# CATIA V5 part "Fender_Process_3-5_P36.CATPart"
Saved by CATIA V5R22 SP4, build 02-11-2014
Part number: Fender
Bounding box of the stored display mesh (mm): x -800 to 0, y -40 to 122.298, z 0 to 580
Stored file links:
  C:\DATA\Car_ASSY\教育モデル\3_SOL\Fender_Process_3-5_P36.CATPart
  C:\DATA\Car_ASSY\教育モデル\3_SOL\Car_Fender.CATPart
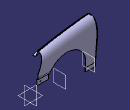
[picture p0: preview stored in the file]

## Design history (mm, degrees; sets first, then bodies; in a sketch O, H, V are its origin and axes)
Set1
  Plane1: type Offset, RefPlane yz-plane, Offset 400, reversed
  Plane2: type Offset, RefPlane Plane1, Offset 400, reversed
Body1 (main body)
Body2
  Sketch1 on yz-plane, origin (0, 0, 0), H (0, 1, 0), V (0, 0, 1)
    point P4 (100, 50)
    point P5 (10, 450)
    spline S1 through (10, 450) (100, 50)
    line L1 (0, 450) -> (10, 450)
    line L2 (0, 0) -> (0, 450)
    line L3 (100, 0) -> (0, 0)
    line L4 (100, 50) -> (100, 0)
    point P6 (100, 50)
    point P7 (10, 450)
    distance P4 L3 = 50
    distance P5 L2 = 10
    distance L4 L2 = 100
    distance L1 H = 450
    coincidence: L2 V, H L3, P4 P6, P7 P5
  Sketch2 on Plane1, origin (-400, 0, 0), H (0, 1, 0), V (0, 0, 1)
    point P4 (100, 50)
    point P5 (10, 530)
    spline S1 through (10, 530) (100, 50)
    line L1 (0, 530) -> (10, 530)
    line L2 (0, 0) -> (0, 530)
    line L3 (100, 0) -> (0, 0)
    line L4 (100, 50) -> (100, 0)
    point P6 (100, 50)
    point P7 (10, 530)
    distance P4 L3 = 50
    distance P5 L2 = 10
    distance L4 L2 = 100
    distance L1 H = 530
    coincidence: L2 V, H L3, P4 P6, P7 P5
  Sketch3 on Plane2, origin (-800, 0, 0), H (0, 1, 0), V (0, 0, 1)
    point P4 (100, 50)
    point P5 (10, 580)
    spline S1 through (10, 580) (100, 50)
    line L1 (0, 580) -> (10, 580)
    line L2 (0, 0) -> (0, 580)
    line L3 (100, 0) -> (0, 0)
    line L4 (100, 50) -> (100, 0)
    point P6 (100, 50)
    point P7 (10, 580)
    distance P4 L3 = 50
    distance P5 L2 = 10
    distance L4 L2 = 100
    distance L1 H = 580
    coincidence: L2 V, H L3, P4 P6, P7 P5
  Loft1: solid, Sections (Sketch1; Sketch2; Sketch3)
  Body3
    Sketch4 on zx-plane, origin (0, 0, 0), H (-1, 0, 0), V (0, 0, 1)
      line L1 (-46.4952, 240) -> (159.0779, 240)
      arc A1 centre (390, 110) radius 265 from (159.0779, 240) to (655, 109.9999) cw
      point P2 (390, 110)
      line L2 (655, 109.9999) -> (655, -30)
      line L3 (-46.4952, 626.6258) -> (850, 626.6258)
      line L4 (850, 626.6258) -> (850, -30)
      line L5 (850, -30) -> (655, -30)
      line L6 (-46.4952, 626.6258) -> (-46.4952, 240)
      radius A1 = 265
      distance P2 H = 110
      distance V P2 = 390
      distance H L1 = 240
      horizontal: L1 H, L3 H, L5 H
      tangency: L2 A1
      vertical: L2 V, L4 V, L6 V
    Pad1: profile Sketch4, direction (0, 1, 0), length 340, mirrored extent
  Intersect1: tool Body3
  Shell1: ExtOffset 0, Face (face of Loft1; face of Loft1; face of Pad1 from Sketch4.A1; face of Pad1 from Sketch4.L1; face of Loft1; face of Loft1), IntOffset 3
  Sketch5 on Plane2, origin (-800, 0, 0), H (0, 1, 0), V (0, 0, 1)
    line L1 (0, 580) -> (0, 545)
    line L2 (-5, 540) -> (-40, 540)
    point P2 (-40, 540)
    reference projected line E1 (10, 580) -> (0, 580)
    reference intersected line E2 (0, 0) -> (0, 580)
    arc A1 centre (-5, 545) radius 5 from (-5, 540) to (0, 545) ccw
    line L3 (-5, 537) -> (-40, 537)
    arc A2 centre (-5, 545) radius 8 from (-5, 537) to (3, 545) ccw
    line L4 (3, 580) -> (3, 545)
    line L5 (-40, 537) -> (-40, 540)
    line L6 (3, 580) -> (0, 580)
    reference projected line E3 (10, 580) -> (0, 580)
    distance E1 L2 = 40
    radius A1 = 5
    distance L1 P2 = 40
    length L5 = 3
    length L6 = 3
    radius A2 = 8
    vertical: L1 V, L4 V, L5 V
    horizontal: L2 H, L6 H, L3 H
    coincidence: L1 E2, L6 E3
    tangency: A1 L2, A1 L1, L4 A2, A2 L3
  Rib1: profile Sketch5, centre curve edge [face of Loft1 | face of Loft1]
  Sketch6 on Plane2, origin (-800, 0, 0), H (0, 1, 0), V (0, 0, 1)
    projected curve E1
    projected line E2 (10, 576.9862) -> (3, 576.9862)
    point P4 (3, 576.9862)
    projected line E3 (3, 576.9862) -> (3, 545)
    projected line E4 (3, 576.9862) -> (3, 399.233)
    point P5 (3, 576.9862)
    projected line E5 (97, 0) -> (97, 50)
    line L1 (97, 0) -> (37, 0)
    line L2 (37, 0) -> (17.9077, 155.4943)
    arc A1 centre (2003, 399.233) radius 2000 from (3, 399.233) to (17.9077, 155.4943) ccw
    angle L1 L2 = 97
    length L1 = 60
    radius A1 = 2000
    horizontal: L1 H
    tangency: A1 E3, A1 L2
    coincidence: P4 P5
  Pad2: profile Sketch6, direction (1, 0, 0), length 10, opposite side length -7
  Sketch7 on yz-plane, origin (0, 0, 0), H (0, 1, 0), V (0, 0, 1)
    projected curve E1
    projected curve E2
    point P1 (103.8705, 240)
    line L1 (100.927, 243) -> (92.1161, 243)
    line L2 (86.1161, 237) -> (86.1161, 160)
    line L3 (86.1161, 160) -> (89.1161, 160)
    line L4 (89.1161, 160) -> (89.1161, 237)
    point P5 (103.8705, 240)
    line L5 (101.1109, 260) -> (104.111, 260)
    point P6 (101.1109, 260)
    point P7 (104.111, 260)
    offset curve E3
    offset curve E4
    line L6 (92.1161, 240) -> (103.8705, 240)
    arc A1 centre (92.1161, 237) radius 3 from (92.1161, 240) to (89.1161, 237) ccw
    arc A2 centre (92.1161, 237) radius 6 from (92.1161, 243) to (86.1161, 237) ccw
    distance L4 L2 = 3
    distance L4 E1 = 15
    distance L1 L6 = 3
    radius A1 = 3
    radius A2 = 6
    distance L6 L3 = 80
    distance L5 L6 = 20
    horizontal: L1 H, L3 H, L5 H, L6 H
    vertical: L2 V, L4 V
    coincidence: P7 E1, E3 P6, P6 L5, P7 L5, P5 P1
    tangency: A1 L6, A1 L4, A2 L1, A2 L2
  Rib2: profile Sketch7, centre curve edge [face of Pad1 from Sketch4.L1 | face of Shell1]
  Body4
    Sketch8 on zx-plane, origin (0, 0, 0), H (-1, 0, 0), V (0, 0, 1)
      point P1 (0, 300)
      line L1 (0, 300) -> (127.0171, 520)
      line L2 (127.0171, 520) -> (-100, 520)
      line L3 (-100, 520) -> (-100, 300)
      line L4 (-100, 300) -> (0, 300)
      angle L1 L4 = 120
      distance L4 H = 300
      coincidence: P1 V
      horizontal: L2 H, L4 H
      vertical: L3 V
    Pad3: profile Sketch8, direction (0, 1, 0), length 220, mirrored extent
  Remove1: tool Body4
  Sketch9 on xy-plane, origin (0, 0, 0), H (1, 0, 0), V (0, 1, 0)
    line L1 (-730, -50.1266) -> (-730, -25)
    arc A1 centre (-725, -25) radius 5 from (-730, -25) to (-720, -25) cw
    point P3 (-725, -25)
    line L2 (-720, -25) -> (-720, -50.1266)
    line L3 (-720, -50.1266) -> (-730, -50.1266)
    reference projected line E1 (-5.7993, -40) -> (-800, -40)
    reference projected line E2 (-800, -40) -> (-800, -5)
    radius A1 = 5
    distance P3 E1 = 15
    distance P3 E2 = 75
    vertical: L1 V, L2 V
    tangency: A1 L1, L2 A1
    horizontal: L3 H
  Pocket1: profile Sketch9, direction (0, 0, 1), length 660
  RectPattern1: of Pocket1, direction 1 instances 3, spacing 270, along X axis
  Sketch10 on {plane type Tangent, Support face of Rib2, RefPoint {point type OnSurface, Support face of Rib2, RefPoint {point stored without definition}, Length 0, Direction (0, 0, -1000)}}, origin (-91.1264, 90.6031, 191.8753), H (0.9999, -0.0141, 0), V (0, 0, 1)
    point P1 (41.1384, -1.8753)
    reference projected line E1 (91.1384, -31.8753) -> (91.1384, 45.1247) from edge [face of Rib2 | face of Rib2]
    reference projected line E2 (-67.8506, -31.8753) -> (91.1384, -31.8753) from edge [face of Rib2 | face of Rib2]
    distance P1 E1 = 50
    distance P1 E2 = 30
  Hole1: placed by Sketch10, at (-49.9928, 89.9835, 190) direction (-0.016, -0.9999, 0), diameter 15, through (limit type 3)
